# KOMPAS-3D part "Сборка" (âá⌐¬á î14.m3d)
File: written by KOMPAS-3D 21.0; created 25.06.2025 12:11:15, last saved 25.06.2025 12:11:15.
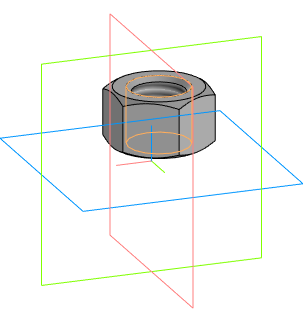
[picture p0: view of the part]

Document properties: Автор: PC321; Полное имя файла: C:\Users\PC321\Desktop\Гайка М14.m3d

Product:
- Part/product: Сборка
    Масса: 0.02533
  - Component [standard]: Гайка М14-6H(S21) ГОСТ 5915-70  | pos. 1  | Масса: 0.02533; Раздел спецификации: Стандартные изделия; Рассекать на разрезах: no; additional columns: М14-6H (S21)

Referenced files in C:\Program Files\ASCON\KOMPAS-3D v21 Study\Libs\PARTLib\DATA\vault\Methods\Kompas\3D\: PLib_Nut_OST92_900.m3d
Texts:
  bcut1
  hole1
  hcut1
  hole2
  cut1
